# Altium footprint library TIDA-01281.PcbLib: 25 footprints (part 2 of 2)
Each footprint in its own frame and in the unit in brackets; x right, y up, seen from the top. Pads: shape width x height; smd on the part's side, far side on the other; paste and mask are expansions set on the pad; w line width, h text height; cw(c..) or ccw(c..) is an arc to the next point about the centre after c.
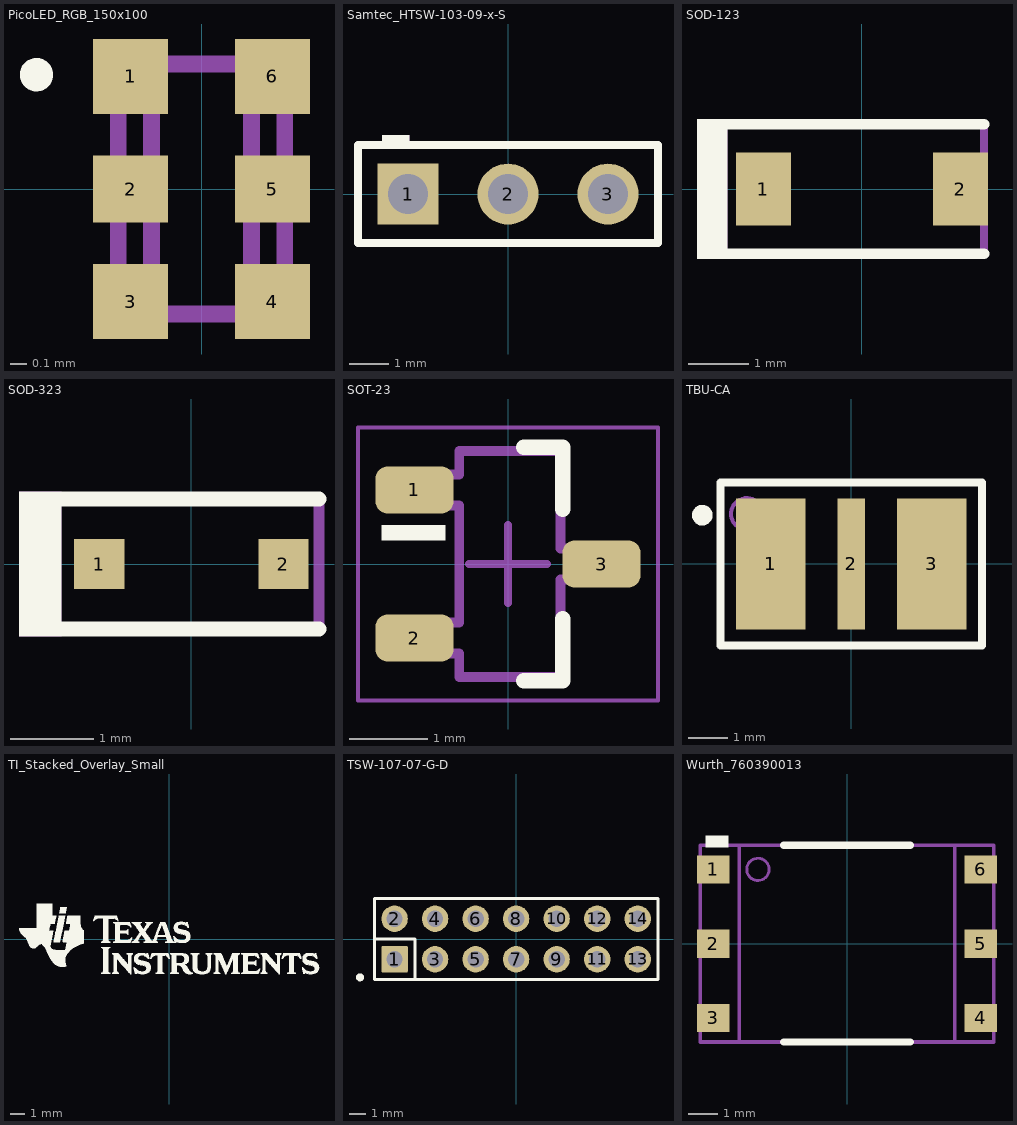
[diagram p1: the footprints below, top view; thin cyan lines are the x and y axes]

## PicoLED_RGB_150x100 [mm] "SMD, 6-Leads, Body 1.5x1mm"
height 0.25
pads (6):
  rect 0.45x0.45 smd: 1(-0.425,0.675) 3(-0.425,-0.675) 4(0.425,-0.675) 6(0.425,0.675)
  rect 0.45x0.4 smd: 2(-0.425,0) 5(0.425,0)
Top Overlay:
  circle w0.1: c-0.991,0.686 r0.05
Mechanical 5:
  lines w0.1: -0.3,-0.75 -0.3,0.75 ; 0.3,-0.75 0.3,0.75 ; -0.5,-0.75 -0.5,0.75 0.5,0.75 0.5,-0.75 -0.5,-0.75
  text ".Designator" at -0.838,-2.769 h0.76
3D body: height 0.08, standoff 0, extent -0.5,-0.75 0.5,0.75
3D body: height 0.25, standoff 0.08, extent -0.3,-0.75 0.3,0.75

## Samtec_HTSW-103-09-x-S [mm] "Header, 3x1, 2.54mm, TH"
height 8.382
pads (3):
  rect 1.55x1.55 hole 1.016: 1(-2.54,0)
  round 1.55 hole 1.016: 2(0,0) 3(2.54,0)
Top Overlay:
  rectangle: -3.2,1.245 -2.5,1.5
  lines w0.2: -3.81,-1.245 3.81,-1.245 3.81,1.245 -3.81,1.245 -3.81,-1.245
Mechanical 5:
  rectangle: -3.2,1.245 -2.5,1.5
  lines w0.1: -3.81,-1.245 -3.81,1.245 3.81,1.245 3.81,-1.245 -3.81,-1.245
  text ".Designator" at 0.711,0.33 h0.76
3D body: height 8.38, standoff -10.16, extent -3.81,-1.245 3.81,1.245

## SOD-123 [mm] "On Semi recommended land pattern"
height 1.35
pads (2):
  rect 0.915x1.22 smd: 1(-1.637,0) 2(1.637,0)
Top Overlay:
  rectangle: -2.743,-1.168 -2.235,1.168
  lines w0.178: -2.413,-1.079 2.032,-1.079 ; -2.413,1.079 2.032,1.079
Mechanical 5:
  rectangle: -2.743,-1.168 -2.235,1.168
  lines w0.127: -2.413,-1.079 2.032,-1.079 2.032,1.079 -2.413,1.079
  text ".Designator" at 0.127,-0.635 h0.76
3D body: height 1.35, standoff 0, extent -1.932,-0.9 1.932,0.9

## SOD-323 [mm] "NXP recommended land pattern"
height 1.15
pads (2):
  rect 0.6x0.6 smd paste-0.05: 1(-1.1,0) 2(1.1,0)
Top Overlay:
  rectangle: -2.057,-0.864 -1.549,0.864
  lines w0.178: -1.803,-0.775 0.1,-0.775 1.525,-0.775 ; -1.803,0.775 0.1,0.775 1.525,0.775
Mechanical 5:
  rectangle: -2.057,-0.864 -1.549,0.864
  lines w0.127: -1.803,-0.775 0.1,-0.775 1.525,-0.775 1.525,0.775 0.1,0.775 -1.803,0.775
  text ".Designator" at -1.4,-0.275 h0.76
3D body: height 1.1, standoff 0, extent -1.3,-0.675 1.3,0.675

## SOT-23 [mm] "SOT23, 3-Leads, Body 2.9x1.3mm, Pitch 0.95mm, Lead Span 2.5mm, IPC Medium Density"
height 1.1
pads (3):
  rrect50% 1x0.6 smd: 1(-1.2,0.95) 2(-1.2,-0.95) 3(1.2,0)
Top Overlay:
  rectangle: -1.625,0.3 -0.8,0.5
  lines w0.2: 0.2,-1.5 0.7,-1.5 0.7,-0.7 ; 0.2,1.5 0.7,1.5 0.7,0.7
Mechanical 5:
  lines w0.127: -1.16,-1.15 -1.16,-0.75 -0.625,-0.75 -0.625,0.75 -1.16,0.75 -1.16,1.15 -0.625,1.15 -0.625,1.45 0.675,1.45 0.675,0.2 1.21,0.2 1.21,-0.2 0.675,-0.2 0.675,-1.45 -0.625,-1.45 -0.625,-1.15 -1.16,-1.15
  text ".Designator" at 0.381,-0.381 h0.76
Mechanical 15:
  lines w0.05: -1.925,-1.75 1.925,-1.75 1.925,1.75 -1.925,1.75 -1.925,-1.75
  lines w0.1: -0.5,0 0.5,0 ; 0,-0.5 0,0.5
3D body: height 1, standoff 0, extent -1.16,-1.45 1.21,1.45

## TBU-CA [mm] "Bourns"
height 0.9
pads (3):
  rect 1.75x3.3 smd paste-0.012 mask+0.05: 1(-2.025,0) 3(2.025,0)
  rect 0.7x3.3 smd paste-0.012 mask+0.05: 2(0,0)
Top Overlay:
  circle w0.254: c-3.755,1.23 r0.133
  lines w0.2: -3.3,-2.05 3.3,-2.05 3.3,2.05 -3.3,2.05 -3.3,-2.05
Mechanical 5:
  circle w0.1: c-2.631,1.263 r0.399
  lines w0.1: -3.3,-2.05 3.3,-2.05 3.3,2.05 -3.3,2.05 -3.3,-2.05
  text ".Designator" at -0.383,-0.421 h0.76
3D body: height 0.87, standoff 0.86, extent -2.829,1.064 -2.431,1.463
3D body: height 0.87, standoff -0.01, extent -3.25,-2 3.25,2

## TI_Stacked_Overlay_Small [mm]
Top Overlay:
  drawing of 18 lines, arcs and shapes, not listed

## TSW-107-07-G-D [mm] "Samtec 100mil, 2x7, 230 mil above insulator"
height 8.382
pads (14):
  rrect6% 1.65x1.65 hole 1.016: 1(-7.62,-1.27)
  round 1.65 hole 1.016: 2(-7.62,1.27) 3(-5.08,-1.27) 4(-5.08,1.27) 5(-2.54,-1.27) 6(-2.54,1.27) 7(0,-1.27) 8(0,1.27) 9(2.54,-1.27) 10(2.54,1.27) 11(5.08,-1.27) 12(5.08,1.27) 13(7.62,-1.27) 14(7.62,1.27)
Top Overlay:
  circle w0.25: c-9.79,-2.4 r0.125
  lines w0.178: -8.89,0 -6.35,0 -6.35,-2.54 ; -8.89,-2.54 8.89,-2.54 8.89,2.54 -8.89,2.54 -8.89,-2.54
Mechanical 5:
  rectangle: -8.128,-1.778 -7.112,-0.762
  lines w0.127: -8.89,-2.54 -8.89,2.54 8.89,2.54 8.89,-2.54 -8.89,-2.54
  text ".Designator" at 0.203,-0.762 h1.02
3D body: height 8.38, standoff -2.54, extent -8.89,-2.54 8.89,2.54

## Wurth_760390013 [mil] "Wurth"
height 165
pads (6):
  rect 44x38 smd: 1(-180,100) 2(-180,0) 3(-180,-100) 4(180,-100) 5(180,0) 6(180,100)
Top Overlay:
  region: -190,145 -160,145 -160,130 -190,130
  lines w10: -85,-132.5 85,-132.5 ; -85,132.5 85,132.5
Mechanical 5:
  circle w3.94: c-120,100 r15
  lines w5: -145,-130 -145,130 ; 145,-130 145,130 ; -197.5,-132.5 -197.5,132.5 197.5,132.5 197.5,-132.5 -197.5,-132.5
  text ".Designator" at -70,-15 h40
3D body: height 20, standoff 0, extent 143.75,-115 196.25,-85
3D body: height 20, standoff 0, extent 145,-15 197.5,15
3D body: height 20, standoff 0, extent 145,85 197.5,115
3D body: height 20, standoff 0, extent -197.63,-115 -145,-85
3D body: height 20, standoff 0, extent -197.63,-15 -145,15
3D body: height 20, standoff 0, extent -197.14,85 -145,115
3D body: height 165, standoff 0, extent -145.29,-135.2 145.2,130.29
3D body: height 165.5, standoff 150, extent -135.27,84.73 -104.72,115.28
